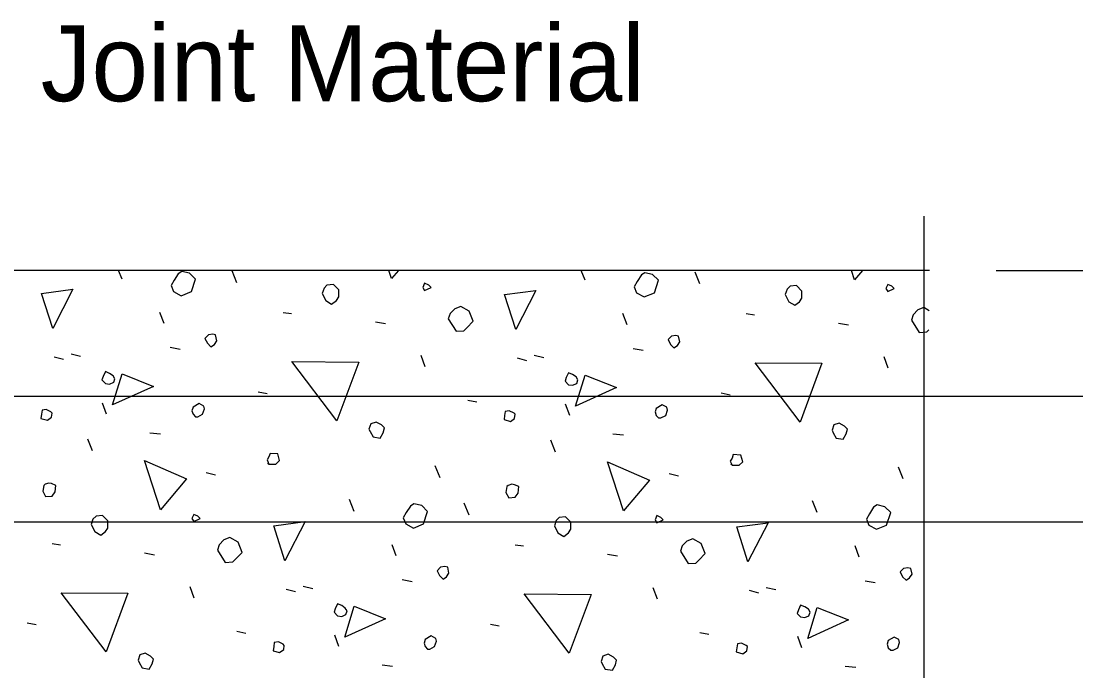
# Model space of a CAD drawing. Extents: x -7.9 to 27, y -3.1 to 14.6.
# Drawn here: x 4.543 to 5.593, y 4.404 to 5.05 of the extents above; entities that cross this region are included whole.
import ezdxf

# ---------------------------------------------------------------- set-up
doc = ezdxf.new("R2010")
doc.units = 0
for name, color, linetype in [('Border', 7, 'Continuous'), ('Patterning', 7, 'Continuous'), ('PlotBorder_dp', 7, 'Continuous'), ('TextMisc', 7, 'Continuous')]:
    doc.layers.add(name, color=color, linetype=linetype)

msp = doc.modelspace()

# ---------------------------------------------------------------- linework, layer by layer
at = {"layer": 'Patterning'}
msp.add_line((5.4469, 4.8024), (4.067, 4.8024), dxfattribs=at)
at = {"layer": 'PlotBorder_dp'}
for p, q in [((5.5134, 4.8024), (6.0669, 4.8024)), ((4.0712, 4.6774), (6.0669, 4.6774)), ((3.8875, 4.5524), (6.0669, 4.5524))]:
    msp.add_line(p, q, dxfattribs=at)
msp.add_lwpolyline([(5.4416, 3.9158), (5.4416, 4.2171), (5.4918, 4.2171), (5.3945, 4.2602), (5.4416, 4.2602), (5.4416, 4.8565)], dxfattribs=at)
at = {"layer": 'TextMisc'}
for p, q in [((4.6434, 4.7937), (4.6399, 4.8024)), ((4.7577, 4.7902), (4.753, 4.802)), ((5.1042, 4.7926), (5.1003, 4.8024)), ((5.2185, 4.789), (5.2138, 4.8008)), ((5.5134, 4.8024), (6.0669, 4.8024)), ((4.6853, 4.7495), (4.6811, 4.7607)), ((4.8037, 4.7607), (4.8119, 4.7596)), ((5.1461, 4.7484), (5.1419, 4.7596)), ((5.2645, 4.7596), (5.2727, 4.7584)), ((4.8956, 4.7513), (4.9056, 4.7495)), ((5.3564, 4.7501), (5.3664, 4.7484)), ((4.6912, 4.726), (4.7012, 4.7242)), ((5.1519, 4.7248), (5.162, 4.723)), ((4.5757, 4.7165), (4.5851, 4.7142)), ((4.5927, 4.7195), (4.6022, 4.7171)), ((4.9451, 4.7065), (4.941, 4.7177)), ((5.0365, 4.7154), (5.0459, 4.713)), ((5.0535, 4.7183), (5.063, 4.716)), ((5.4059, 4.7053), (5.4018, 4.7165)), ((4.7789, 4.6818), (4.7878, 4.68)), ((4.9875, 4.6735), (4.9964, 4.6718)), ((5.2397, 4.6806), (5.2486, 4.6788)), ((4.6281, 4.6594), (4.624, 4.6706)), ((5.0889, 4.6582), (5.0848, 4.6694)), ((4.6711, 4.6411), (4.6817, 4.6399)), ((5.1319, 4.6399), (5.1425, 4.6388)), ((4.614, 4.6229), (4.6092, 4.6346)), ((5.0748, 4.6217), (5.07, 4.6335)), ((4.9599, 4.5963), (4.9551, 4.6081)), ((4.7271, 4.6016), (4.7365, 4.5993)), ((5.1879, 4.6005), (5.1973, 4.5981)), ((5.4206, 4.5952), (5.4159, 4.6069)), ((4.8744, 4.5627), (4.8697, 4.5745)), ((4.9887, 4.5592), (4.984, 4.571)), ((5.3352, 4.5616), (5.3305, 4.5734)), ((4.5739, 4.5309), (4.5821, 4.5297)), ((4.9162, 4.5186), (4.9121, 4.5297)), ((5.0347, 4.5297), (5.0429, 4.5286)), ((5.377, 4.5174), (5.3729, 4.5286)), ((4.6658, 4.5215), (4.6758, 4.5197)), ((5.1266, 4.5203), (5.1366, 4.5186)), ((4.9221, 4.495), (4.9322, 4.4932)), ((5.3829, 4.4938), (5.393, 4.492)), ((4.7153, 4.4767), (4.7112, 4.4879)), ((4.8066, 4.4856), (4.8161, 4.4832)), ((4.8237, 4.4885), (4.8332, 4.4861)), ((5.1761, 4.4755), (5.172, 4.4867)), ((5.2674, 4.4844), (5.2769, 4.482)), ((5.2845, 4.4873), (5.294, 4.485)), ((4.5491, 4.452), (4.558, 4.4502)), ((5.0099, 4.4508), (5.0188, 4.449)), ((4.7577, 4.4437), (4.7666, 4.4419)), ((5.2185, 4.4425), (5.2274, 4.4408)), ((4.8591, 4.4284), (4.855, 4.4396)), ((5.3199, 4.4272), (5.3158, 4.4384)), ((4.9021, 4.4101), (4.9127, 4.409)), ((5.3629, 4.409), (5.3735, 4.4078))]:
    msp.add_line(p, q, dxfattribs=at)
for points in [[(4.6947, 4.7814), (4.7023, 4.7772), (4.7124, 4.7814), (4.7165, 4.7937), (4.7106, 4.7996), (4.7029, 4.8014), (4.6994, 4.799), (4.6953, 4.7926), (4.6923, 4.7873), (4.6947, 4.7814)], [(4.9115, 4.7943), (4.9089, 4.8024)], [(4.9184, 4.8024), (4.9115, 4.7943)], [(5.1555, 4.7802), (5.1631, 4.7761), (5.1732, 4.7802), (5.1773, 4.7926), (5.1714, 4.7984), (5.1637, 4.8002), (5.1602, 4.7979), (5.1561, 4.7914), (5.1531, 4.7861), (5.1555, 4.7802)], [(5.3723, 4.7931), (5.3693, 4.8024)], [(5.3802, 4.8024), (5.3723, 4.7931)], [(4.8426, 4.7796), (4.8461, 4.7725), (4.852, 4.769), (4.8567, 4.7725), (4.8591, 4.7761), (4.8591, 4.7831), (4.8538, 4.7884), (4.8473, 4.7878), (4.8444, 4.7849), (4.8426, 4.7796)], [(4.9445, 4.7825), (4.951, 4.7855), (4.9487, 4.7878), (4.9445, 4.7896), (4.9428, 4.7855), (4.9445, 4.7825)], [(5.3034, 4.7784), (5.3069, 4.7713), (5.3128, 4.7678), (5.3175, 4.7713), (5.3199, 4.7749), (5.3199, 4.7819), (5.3146, 4.7873), (5.3081, 4.7867), (5.3052, 4.7837), (5.3034, 4.7784)], [(5.4053, 4.7814), (5.4118, 4.7843), (5.4095, 4.7867), (5.4053, 4.7884), (5.4036, 4.7843), (5.4053, 4.7814)], [(4.5745, 4.7448), (4.5633, 4.7796), (4.5945, 4.7837), (4.5745, 4.7448)], [(5.0353, 4.7436), (5.0241, 4.7784), (5.0553, 4.7825), (5.0353, 4.7436)], [(4.9681, 4.7543), (4.9758, 4.7419), (4.9834, 4.7425), (4.9864, 4.7454), (4.9928, 4.7519), (4.9887, 4.7619), (4.9805, 4.7666), (4.9746, 4.7643), (4.9699, 4.7596), (4.9681, 4.7543)], [(5.4465, 4.7624), (5.4413, 4.7655), (5.4354, 4.7631), (5.4307, 4.7584), (5.4289, 4.7531)], [(5.4289, 4.7531), (5.4366, 4.7407), (5.4442, 4.7413), (5.4464, 4.7434)], [(4.7283, 4.7301), (4.7318, 4.7266), (4.7353, 4.7289), (4.7377, 4.7325), (4.7365, 4.7383), (4.7336, 4.7389), (4.7295, 4.7383), (4.7259, 4.7348), (4.7283, 4.7301)], [(5.1891, 4.7289), (5.1926, 4.7254), (5.1961, 4.7277), (5.1985, 4.7313), (5.1973, 4.7372), (5.1944, 4.7378), (5.1903, 4.7372), (5.1867, 4.7336), (5.1891, 4.7289)], [(4.8573, 4.6529), (4.8125, 4.7118), (4.8791, 4.7112), (4.8573, 4.6529)], [(5.3181, 4.6517), (5.2733, 4.7106), (5.3399, 4.7101), (5.3181, 4.6517)], [(4.6269, 4.69), (4.631, 4.6894), (4.6352, 4.6912), (4.6363, 4.6947), (4.6346, 4.6977), (4.631, 4.7), (4.6269, 4.7018), (4.6246, 4.6971), (4.6234, 4.6936), (4.6269, 4.69)], [(4.634, 4.6688), (4.6434, 4.6995), (4.6747, 4.6871), (4.634, 4.6688)], [(5.0877, 4.6888), (5.0918, 4.6883), (5.096, 4.69), (5.0971, 4.6936), (5.0954, 4.6965), (5.0918, 4.6989), (5.0877, 4.7006), (5.0854, 4.6959), (5.0842, 4.6924), (5.0877, 4.6888)], [(5.0948, 4.6676), (5.1042, 4.6983), (5.1354, 4.6859), (5.0948, 4.6676)], [(4.5627, 4.6553), (4.5692, 4.6535), (4.5733, 4.6564), (4.5739, 4.6606), (4.5727, 4.6617), (4.568, 4.6641), (4.5639, 4.6635), (4.5633, 4.6594), (4.5627, 4.6553)], [(4.7165, 4.657), (4.7188, 4.657), (4.7236, 4.6594), (4.7253, 4.6647), (4.7247, 4.6676), (4.72, 4.67), (4.7141, 4.6665), (4.713, 4.6629), (4.7141, 4.6594), (4.7165, 4.657)], [(5.0235, 4.6541), (5.03, 4.6523), (5.0341, 4.6553), (5.0347, 4.6594), (5.0335, 4.6606), (5.0288, 4.6629), (5.0247, 4.6623), (5.0241, 4.6582), (5.0235, 4.6541)], [(5.1773, 4.6558), (5.1796, 4.6558), (5.1844, 4.6582), (5.1861, 4.6635), (5.1855, 4.6665), (5.1808, 4.6688), (5.1749, 4.6653), (5.1738, 4.6617), (5.1749, 4.6582), (5.1773, 4.6558)], [(4.8903, 4.6423), (4.8933, 4.637), (4.9003, 4.6358), (4.9033, 4.6411), (4.9045, 4.6458), (4.9015, 4.6488), (4.8962, 4.6517), (4.8909, 4.65), (4.8891, 4.6447), (4.8903, 4.6423)], [(5.3511, 4.6411), (5.3541, 4.6358), (5.3611, 4.6346), (5.3641, 4.6399), (5.3653, 4.6447), (5.3623, 4.6476), (5.357, 4.6505), (5.3517, 4.6488), (5.3499, 4.6435), (5.3511, 4.6411)], [(4.7896, 4.6099), (4.7966, 4.6099), (4.8002, 4.6134), (4.7984, 4.6199), (4.7907, 4.6205), (4.7896, 4.617), (4.7878, 4.614), (4.7896, 4.6099), (4.7884, 4.6111)], [(5.2504, 4.6087), (5.2574, 4.6087), (5.261, 4.6122), (5.2592, 4.6187), (5.2515, 4.6193), (5.2504, 4.6158), (5.2486, 4.6128), (5.2504, 4.6087), (5.2492, 4.6099)], [(4.6817, 4.5645), (4.6658, 4.6134), (4.7076, 4.5952), (4.6817, 4.5645)], [(5.1425, 4.5633), (5.1266, 4.6122), (5.1684, 4.594), (5.1425, 4.5633)], [(4.5645, 4.5828), (4.5674, 4.5775), (4.5739, 4.5781), (4.5768, 4.5822), (4.5774, 4.5887), (4.5733, 4.5904), (4.5704, 4.591), (4.5668, 4.5899), (4.5656, 4.5887), (4.5645, 4.5828)], [(5.0253, 4.5816), (5.0282, 4.5763), (5.0347, 4.5769), (5.0376, 4.581), (5.0382, 4.5875), (5.0341, 4.5893), (5.0312, 4.5899), (5.0276, 4.5887), (5.0264, 4.5875), (5.0253, 4.5816)], [(4.9257, 4.5504), (4.9333, 4.5462), (4.9434, 4.5504), (4.9475, 4.5627), (4.9416, 4.5686), (4.9339, 4.5704), (4.9304, 4.568), (4.9263, 4.5616), (4.9233, 4.5563), (4.9257, 4.5504)], [(5.3865, 4.5492), (5.3941, 4.5451), (5.4042, 4.5492), (5.4083, 4.5616), (5.4024, 4.5675), (5.3947, 4.5692), (5.3912, 4.5669), (5.3871, 4.5604), (5.3841, 4.5551), (5.3865, 4.5492)], [(4.6128, 4.5498), (4.6163, 4.5427), (4.6222, 4.5392), (4.6269, 4.5427), (4.6293, 4.5462), (4.6293, 4.5533), (4.624, 4.5586), (4.6175, 4.558), (4.6145, 4.5551), (4.6128, 4.5498)], [(4.7147, 4.5527), (4.7212, 4.5557), (4.7188, 4.558), (4.7147, 4.5598), (4.713, 4.5557), (4.7147, 4.5527)], [(5.0736, 4.5486), (5.0771, 4.5415), (5.083, 4.538), (5.0877, 4.5415), (5.0901, 4.5451), (5.0901, 4.5521), (5.0848, 4.5574), (5.0783, 4.5569), (5.0753, 4.5539), (5.0736, 4.5486)], [(5.1755, 4.5516), (5.182, 4.5545), (5.1796, 4.5569), (5.1755, 4.5586), (5.1738, 4.5545), (5.1755, 4.5516)], [(4.8055, 4.5138), (4.7943, 4.5486), (4.8255, 4.5527), (4.8055, 4.5138)], [(5.2663, 4.5127), (5.2551, 4.5474), (5.2863, 4.5516), (5.2663, 4.5127)], [(4.7383, 4.5244), (4.746, 4.5121), (4.7536, 4.5127), (4.7566, 4.5156), (4.763, 4.5221), (4.7589, 4.5321), (4.7507, 4.5368), (4.7448, 4.5345), (4.7401, 4.5297), (4.7383, 4.5244)], [(5.1991, 4.5233), (5.2067, 4.5109), (5.2144, 4.5115), (5.2174, 4.5144), (5.2238, 4.5209), (5.2197, 4.5309), (5.2115, 4.5356), (5.2056, 4.5333), (5.2009, 4.5286), (5.1991, 4.5233)], [(4.9593, 4.4991), (4.9628, 4.4956), (4.9663, 4.4979), (4.9687, 4.5015), (4.9675, 4.5074), (4.9646, 4.5079), (4.9604, 4.5074), (4.9569, 4.5038), (4.9593, 4.4991)], [(5.4201, 4.4979), (5.4236, 4.4944), (5.4271, 4.4967), (5.4295, 4.5003), (5.4283, 4.5062), (5.4254, 4.5068), (5.4212, 4.5062), (5.4177, 4.5026), (5.4201, 4.4979)], [(4.6275, 4.4231), (4.5827, 4.482), (4.6493, 4.4814), (4.6275, 4.4231)], [(5.0883, 4.4219), (5.0435, 4.4808), (5.1101, 4.4803), (5.0883, 4.4219)], [(4.8579, 4.459), (4.862, 4.4584), (4.8662, 4.4602), (4.8673, 4.4638), (4.8656, 4.4667), (4.862, 4.4691), (4.8579, 4.4708), (4.8556, 4.4661), (4.8544, 4.4626), (4.8579, 4.459)], [(4.865, 4.4378), (4.8744, 4.4685), (4.9056, 4.4561), (4.865, 4.4378)], [(5.3187, 4.4579), (5.3228, 4.4573), (5.327, 4.459), (5.3281, 4.4626), (5.3264, 4.4655), (5.3228, 4.4679), (5.3187, 4.4696), (5.3164, 4.4649), (5.3152, 4.4614), (5.3187, 4.4579)], [(5.3258, 4.4366), (5.3352, 4.4673), (5.3664, 4.4549), (5.3258, 4.4366)], [(4.7937, 4.4243), (4.8002, 4.4225), (4.8043, 4.4254), (4.8049, 4.4296), (4.8037, 4.4308), (4.799, 4.4331), (4.7949, 4.4325), (4.7943, 4.4284), (4.7937, 4.4243)], [(4.9475, 4.426), (4.9498, 4.426), (4.9545, 4.4284), (4.9563, 4.4337), (4.9557, 4.4366), (4.951, 4.439), (4.9451, 4.4355), (4.9439, 4.4319), (4.9451, 4.4284), (4.9475, 4.426)], [(5.2545, 4.4231), (5.261, 4.4213), (5.2651, 4.4243), (5.2657, 4.4284), (5.2645, 4.4296), (5.2598, 4.4319), (5.2557, 4.4313), (5.2551, 4.4272), (5.2545, 4.4231)], [(5.4083, 4.4249), (5.4106, 4.4249), (5.4153, 4.4272), (5.4171, 4.4325), (5.4165, 4.4355), (5.4118, 4.4378), (5.4059, 4.4343), (5.4047, 4.4308), (5.4059, 4.4272), (5.4083, 4.4249)], [(4.6605, 4.4125), (4.6635, 4.4072), (4.6705, 4.406), (4.6735, 4.4113), (4.6747, 4.416), (4.6717, 4.419), (4.6664, 4.4219), (4.6611, 4.4201), (4.6593, 4.4148), (4.6605, 4.4125)], [(5.1213, 4.4113), (5.1243, 4.406), (5.1313, 4.4048), (5.1343, 4.4101), (5.1354, 4.4148), (5.1325, 4.4178), (5.1272, 4.4207), (5.1219, 4.419), (5.1201, 4.4137), (5.1213, 4.4113)]]:
    msp.add_lwpolyline(points, dxfattribs=at)

# ---------------------------------------------------------------- texts
at = {"layer": 'Border'}
msp.add_text('Poured Joint Material', height=0.0756, dxfattribs=at).set_placement((4.2084, 4.9707))

doc.saveas('drawing.dxf')
